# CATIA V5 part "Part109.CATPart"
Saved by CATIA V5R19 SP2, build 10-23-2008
Part number: MS_04003 (chape arrière side firewall)
Bounding box of the stored display mesh (mm): x -1308.099 to 0, y -314.304 to 0, z 0 to 167.952
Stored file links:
  D:\EPSA\GIT\ELIZ-2022\01 - Maquette CATIA\MS_Miscellanous_Finish_Assembly\MS_A0400 (Firewall)\Part109.CATPart
  D:\EPSA\GIT\ELIZ-2022\01 - Maquette CATIA\MS_Miscellanous_Finish_Assembly\MS_A0400 (Firewall)\MS_A0400 (FireWall).CATProduct
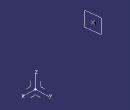
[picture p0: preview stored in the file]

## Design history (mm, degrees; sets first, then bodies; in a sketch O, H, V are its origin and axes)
AxisSystem1: origin (0, 0, 0), X (1, 0, 0), Y (0, 1, 0), Z (0, 0, 1)
Set1
  Point1: type OnCurve, Support Line1, Length 155.604
  Plane1: type Normal, Curve Line1, RefPoint Point1
  Sketch1 on Plane1, origin (-1296.0405, -161.2004, 0.4003), H (-0.1234, 0.9924, 0), V (0.0003, 0, 1)
    circle A1 centre (-154.2898, 167.552) radius 14
    point P1 (-154.2898, 167.552)
    reference projected point E1 (-154.2898, 167.552) from Point1
    radius A1 = 14
    coincidence: P1 E1
Set2
  Line1: linked copy from another document
  DatumSurface1: linked copy from another document
  DatumSurface2: linked copy from another document
Body1 (main body)
  Pad1: profile Sketch1, direction (0.9924, 0.1234, -0.0003), length 50, opposite side length 110
  Point2: type OnSurface, Support face of Pad1 from Sketch1.A1, Length 23.421, Direction (0.131, 0.5823, -0.8024)
  Plane2: type Tangent, Support DatumSurface1, RefPoint Point2
  Point3: type OnPlane, Support Plane2, H -1351.74, V 167.509, Direction (0.9924, 0.1234, 0)
  Line2: type PtPt, FirstPoint Point2, SecondPoint Point3, Start 55, End 24
Body2
  Sketch2 on face of DatumSurface2, origin (13.2848, -107.2449, -18.6878), H (0.9924, 0.1229, 0), V (0.0209, -0.1691, 0.9854)
    reference projected line E1 through (0.074, 191.3929) direction (1, -0.0004) from axis of face of Pad1 from Sketch1.A1
    construction line L1 (-1327.9759, 191.9066) -> (-1327.9859, 165.9066)
    point P3 (-1327.9759, 191.9066)
    reference projected point E2 (-1327.9768, 189.4748) from Point2
    arc A1 centre (-1327.9859, 165.9066) radius 7 from (-1334.9859, 165.9093) to (-1327.9886, 158.9066) ccw
    point P5 (-1327.9886, 158.9066)
    point P6 (-1334.9859, 165.9093)
    line L2 (-1334.9859, 165.9093) -> (-1334.9759, 191.9093)
    point P7 (-1334.9759, 191.9093)
    line L3 (-1334.9759, 191.9093) -> (-1327.9759, 191.9066)
    circle A2 centre (-1327.9859, 165.9066) radius 1.7
    point P8 (-1327.9759, 191.9066)
    point P9 (-1320.9759, 191.9039)
    line L4 (-1320.9759, 191.9039) -> (-1327.9759, 191.9066)
    point P10 (-1320.9859, 165.9039)
    line L5 (-1320.9859, 165.9039) -> (-1320.9759, 191.9039)
    point P11 (-1327.9886, 158.9066)
    arc A3 centre (-1327.9859, 165.9066) radius 7 from (-1320.9859, 165.9039) to (-1327.9886, 158.9066) cw
    radius A1 = 7
    length L2 = 26
    radius A2 = 1.7
    coincidence: P3 E1, L1 E2, P5 L1, P7 E1, P3 P8, P5 P11
    perpendicularity: L1 E1
    tangency: L2 A1
    parallelism: L3 E1, L1 L2
    symmetry: P3 P8 L1, P7 P9 L1, L3 L4 L1, P6 P10 L1, L2 L5 L1, P5 P11 L1, A1 A3 L1
  Pad2: profile Sketch2, direction (0.1211, -0.9779, -0.1704), length 1.5
  Sketch3 on end face of Pad2, origin (13.4665, -108.7117, -18.9434), H (0.9924, 0.1229, 0), V (0.0209, -0.1691, 0.9854)
    intersected line E1 (-1415.9064, 186.5822) -> (-1255.9065, 186.3541) from face of Pad1 from Sketch1.A1
    intersected line E2 (-1415.9023, 197.2991) -> (-1255.9022, 197.4034) from face of Pad1 from Sketch1.A1
    line L1 (-1415.9023, 197.2991) -> (-1415.9064, 186.5822)
    line L2 (-1255.9022, 197.4034) -> (-1255.9065, 186.3541)
  Pocket1: profile Sketch3, direction (-0.1211, 0.9779, 0.1704), up to start face of Pad2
